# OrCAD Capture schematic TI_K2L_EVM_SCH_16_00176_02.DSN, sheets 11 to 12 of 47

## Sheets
11 PAGE35 : K2L_CLK_GEN1: size C; title: CDCM62008 Clk1, 122.88/19.2, Power Filter for Clock,
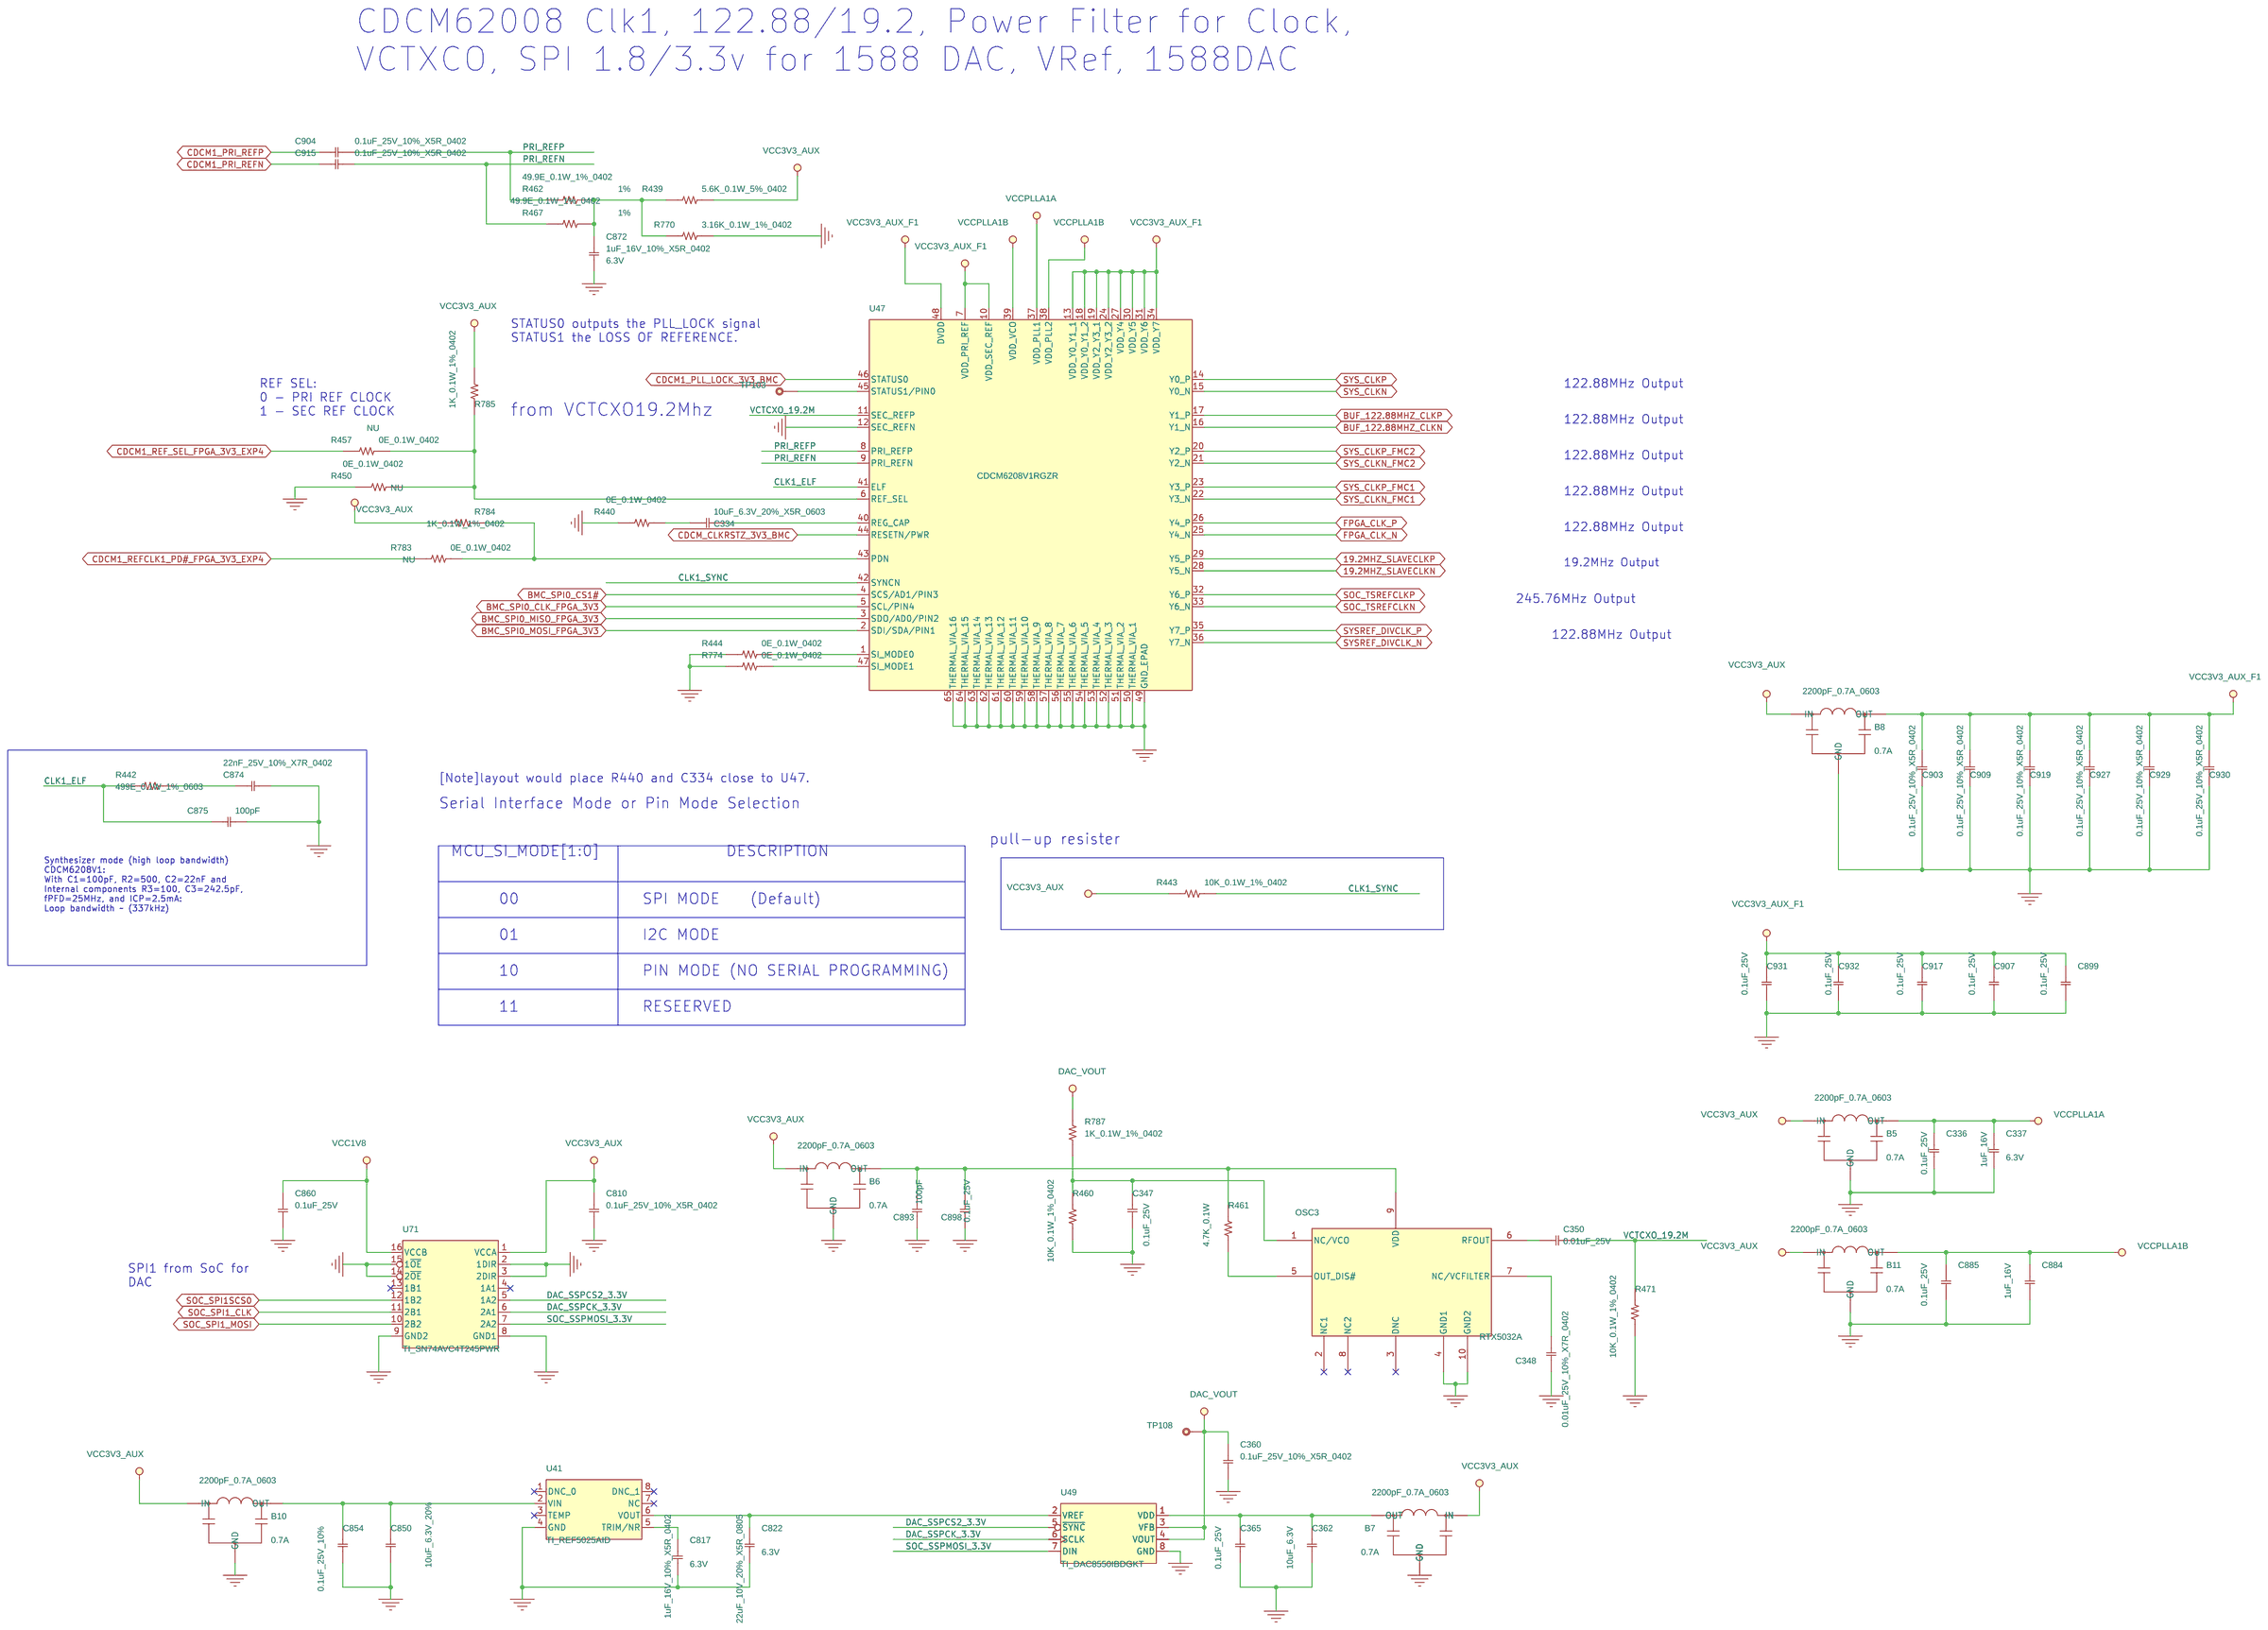
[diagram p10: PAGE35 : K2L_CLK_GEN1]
12 PAGE34 : K2L_ETH_PHY2: size C; title: Ethernet PHY, Magnetics for 2 channel/ Tx/Rx
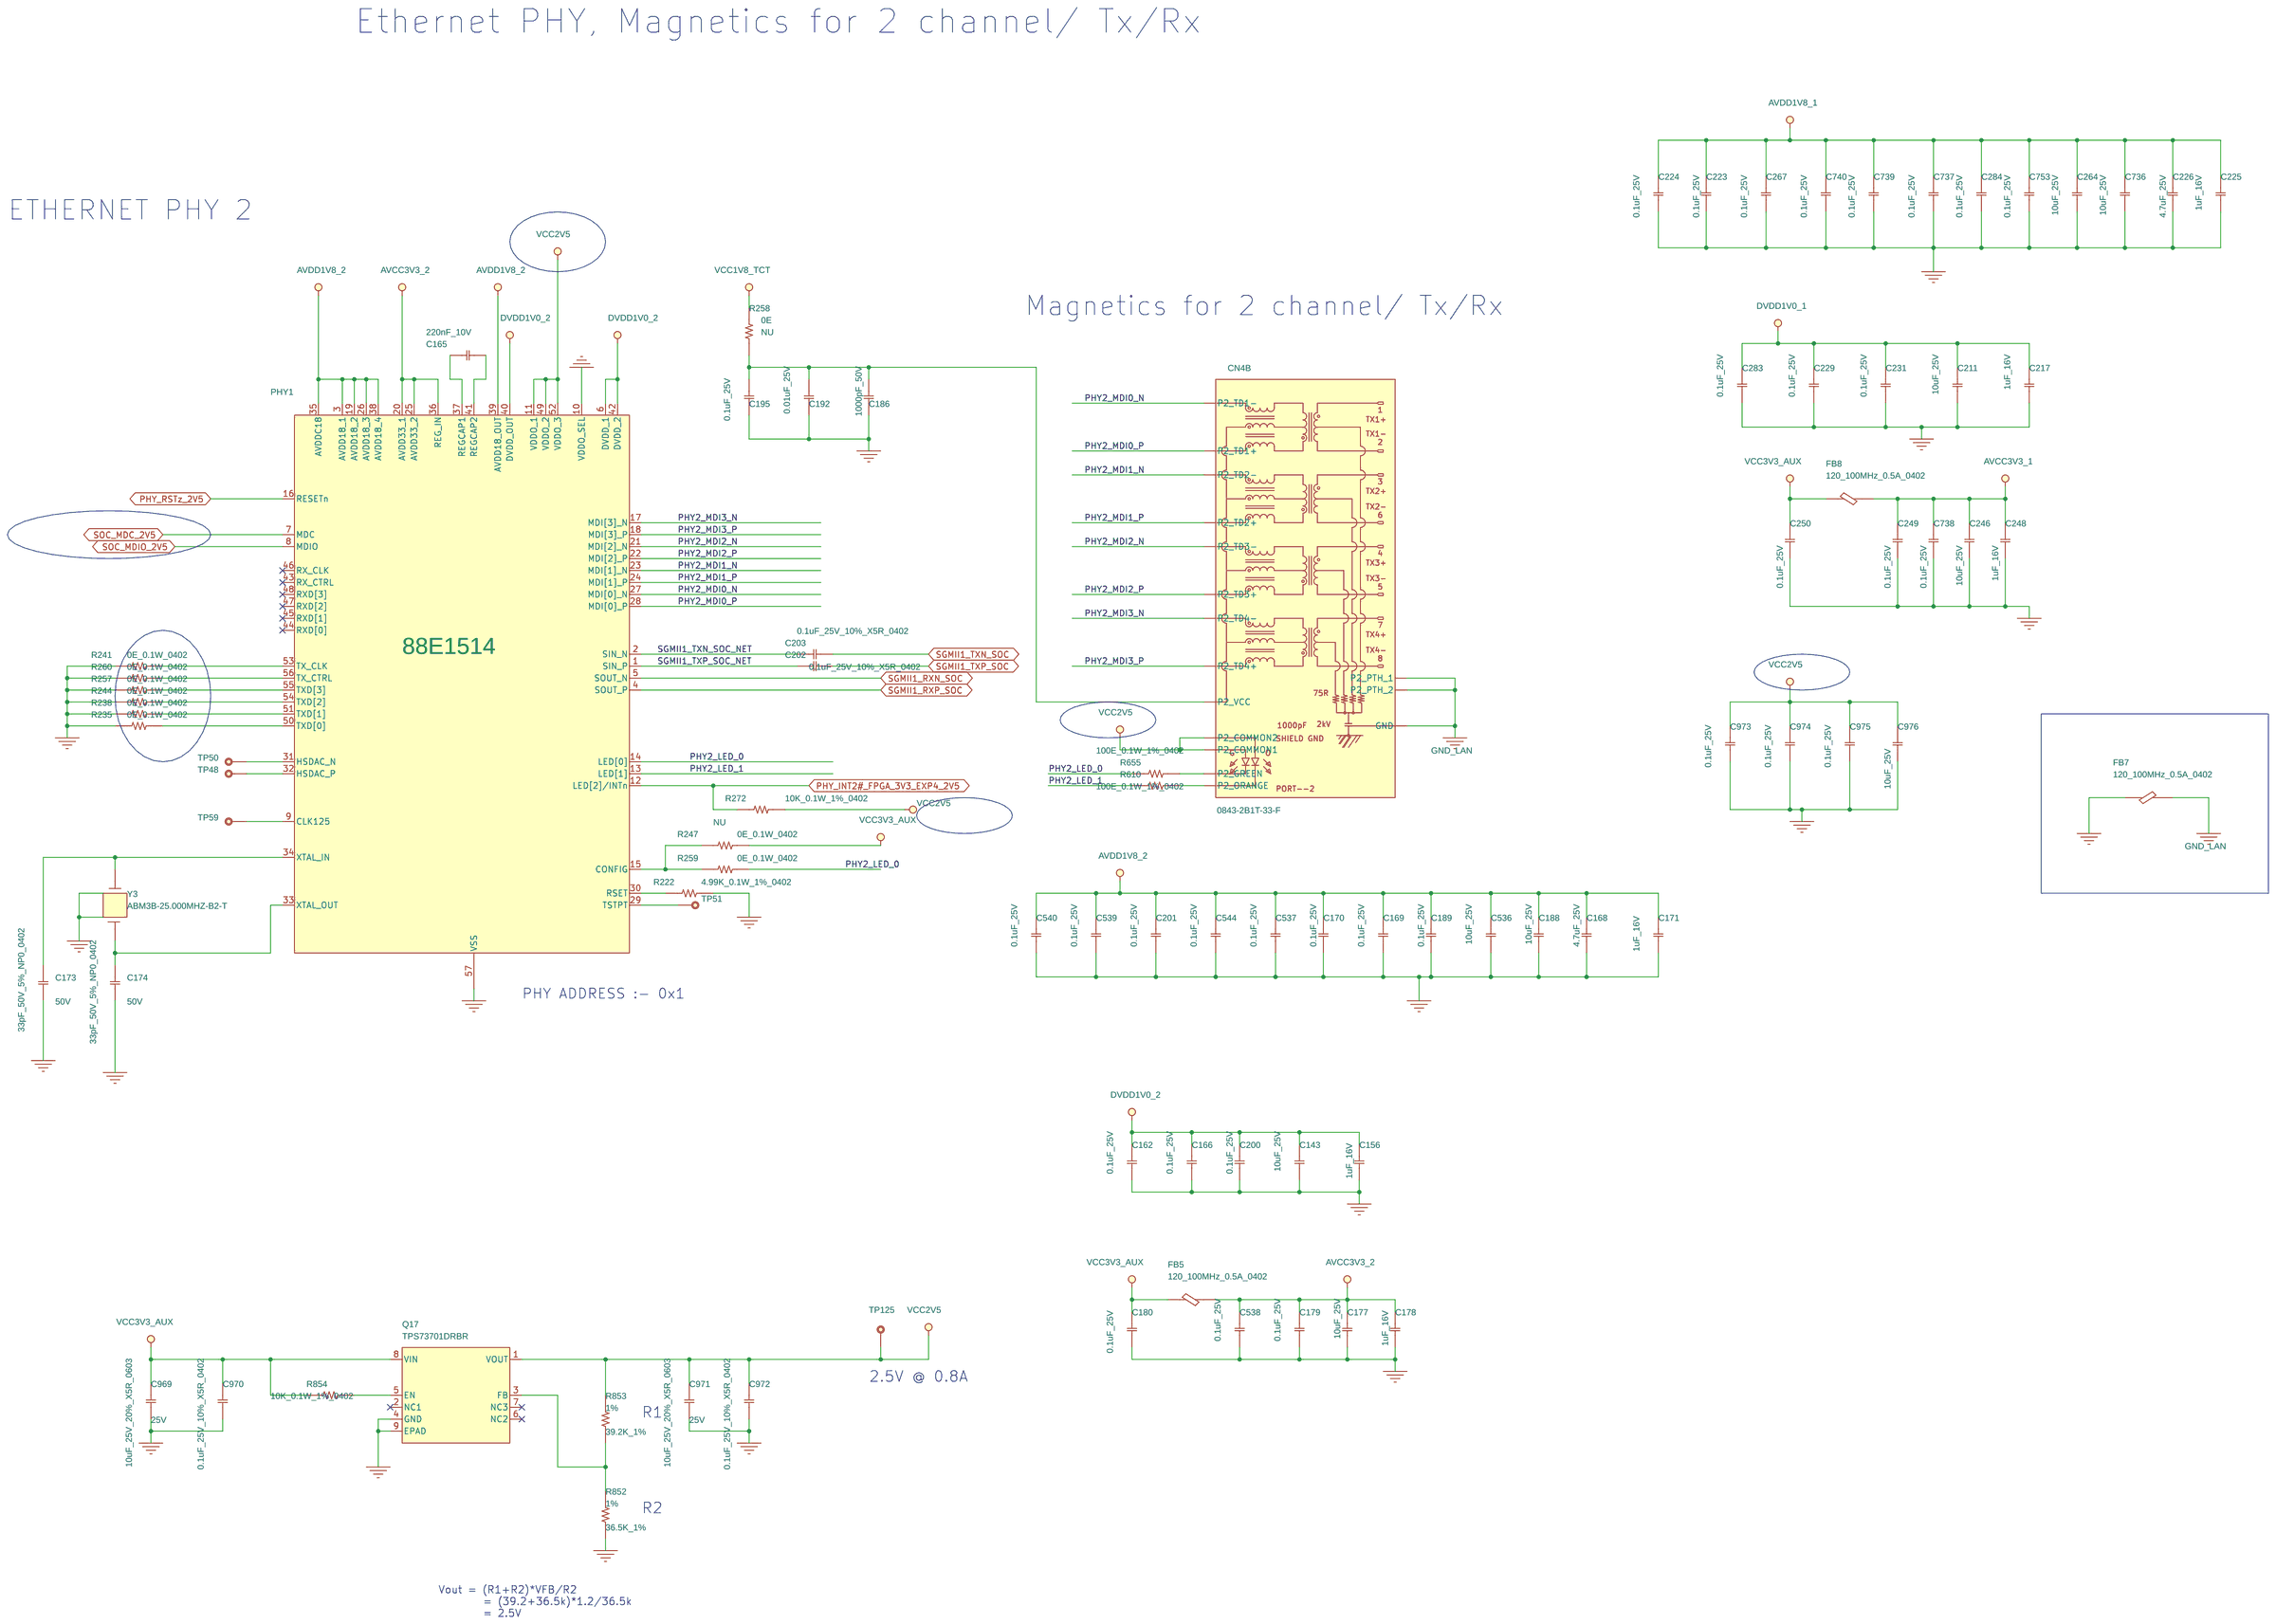
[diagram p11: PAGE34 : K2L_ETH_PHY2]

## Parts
sheet PAGE33 : K2L_ETH_PHY1
CN4  XMH-TRJG17020AENL  [XMULTIPLE_XMH-TRJG17020AENL]  (sections A,B)
sheet PAGE34 : K2L_ETH_PHY2
C143  10uF_25V  [C0603]
C156  1uF_16V  [C0402]
C162  0.1uF_25V  [C0402]
C165  220nF_10V  [C0402]
C166  0.1uF_25V  [C0402]
C168  4.7uF_25V  [C0603]
C169  0.1uF_25V  [C0402]
C170  0.1uF_25V  [C0402]
C171  1uF_16V  [C0402]
C173  33pF_50V_5%_NP0_0402  [C0402]
C174  33pF_50V_5%_NP0_0402  [C0402]
C177  10uF_25V  [C0603]
C178  1uF_16V  [C0402]
C179  0.1uF_25V  [C0402]
C180  0.1uF_25V  [C0402]
C186  1000pF_50V  [C0402]
C188  10uF_25V  [C0603]
C189  0.1uF_25V  [C0402]
C192  0.01uF_25V  [C0402]
C195  0.1uF_25V  [C0402]
C200  0.1uF_25V  [C0402]
C201  0.1uF_25V  [C0402]
C202  0.1uF_25V_10%_X5R_0402  [C0402]
C203  0.1uF_25V_10%_X5R_0402  [C0402]
C211  10uF_25V  [C0603]
C217  1uF_16V  [C0402]
C223  0.1uF_25V  [C0402]
C224  0.1uF_25V  [C0402]
C225  1uF_16V  [C0402]
C226  4.7uF_25V  [C0603]
C229  0.1uF_25V  [C0402]
C231  0.1uF_25V  [C0402]
C246  10uF_25V  [C0603]
C248  1uF_16V  [C0402]
C249  0.1uF_25V  [C0402]
C250  0.1uF_25V  [C0402]
C264  10uF_25V  [C0603]
C267  0.1uF_25V  [C0402]
C283  0.1uF_25V  [C0402]
C284  0.1uF_25V  [C0402]
C536  10uF_25V  [C0603]
C537  0.1uF_25V  [C0402]
C538  0.1uF_25V  [C0402]
C539  0.1uF_25V  [C0402]
C540  0.1uF_25V  [C0402]
C544  0.1uF_25V  [C0402]
C736  10uF_25V  [C0603]
C737  0.1uF_25V  [C0402]
C738  0.1uF_25V  [C0402]
C739  0.1uF_25V  [C0402]
C740  0.1uF_25V  [C0402]
C753  0.1uF_25V  [C0402]
C969  10uF_25V_20%_X5R_0603  [C0603]
C970  0.1uF_25V_10%_X5R_0402  [C0402]
C971  10uF_25V_20%_X5R_0603  [C0603]
C972  0.1uF_25V_10%_X5R_0402  [C0402]
C973  0.1uF_25V  [C0402]
C974  0.1uF_25V  [C0402]
C975  0.1uF_25V  [C0402]
C976  10uF_25V  [C0603]
FB5  120_100MHz_0.5A_0402  [L0402]
FB7  120_100MHz_0.5A_0402  [L0402]
FB8  120_100MHz_0.5A_0402  [L0402]
PHY1  88E1514  [QFN50P800X800X100-57N]
Q17  TPS73701DRBR  [QFN_8P_26_118x118]
R222  4.99K_0.1W_1%_0402  [R0402]
R235  0E_0.1W_0402  [R0402]
R238  0E_0.1W_0402  [R0402]
R241  0E_0.1W_0402  [R0402]
R244  0E_0.1W_0402  [R0402]
R247  0E_0.1W_0402  [R0402]
R257  0E_0.1W_0402  [R0402]
R258  0E  [R0402]
R259  0E_0.1W_0402  [R0402]
R260  0E_0.1W_0402  [R0402]
R272  10K_0.1W_1%_0402  [R0402]
R610  100E_0.1W_1%_0402  [R0402]
R655  100E_0.1W_1%_0402  [R0402]
R852  36.5K_1%  [R0402]
R853  39.2K_1%  [R0402]
R854  10K_0.1W_1%_0402  [R0402]
TP48  TP  [TP-S40]
TP50  TP  [TP-S40]
TP51  TP  [TP-S40]
TP59  TP  [TP-S40]
TP125  Test Point  [TP-S40]
Y3  ABM3B-25.000MHZ-B2-T  [XTAL_ABM3B]
sheet PAGE35 : K2L_CLK_GEN1
B5  2200pF_0.7A_0603  [L_3P_70_63X35]
B6  2200pF_0.7A_0603  [L_3P_70_63X35]
B7  2200pF_0.7A_0603  [L_3P_70_63X35]
B8  2200pF_0.7A_0603  [L_3P_70_63X35]
B10  2200pF_0.7A_0603  [L_3P_70_63X35]
B11  2200pF_0.7A_0603  [L_3P_70_63X35]
C334  10uF_6.3V_20%_X5R_0603  [C0603]
C336  0.1uF_25V  [C0402]
C337  1uF_16V  [C0402]
C347  0.1uF_25V  [C0402]
C348  0.01uF_25V_10%_X7R_0402  [C0402]
C350  0.01uF_25V  [C0402]
C360  0.1uF_25V_10%_X5R_0402  [C0402]
C362  10uF_6.3V  [C0603]
C365  0.1uF_25V  [C0402]
C810  0.1uF_25V_10%_X5R_0402  [C0402]
C817  1uF_16V_10%_X5R_0402  [C0402]
C822  22uF_10V_20%_X5R_0805  [C0805]
C850  10uF_6.3V_20%  [C0603]
C854  0.1uF_25V_10%  [C0402]
C860  0.1uF_25V  [C0402]
C872  1uF_16V_10%_X5R_0402  [C0402]
C874  22nF_25V_10%_X7R_0402  [C0402]
C875  100pF  [C0402]
C884  1uF_16V  [C0402]
C885  0.1uF_25V  [C0402]
C893  100pF  [C0402]
C898  0.1uF_25V  [C0402]
C899  0.1uF_25V  [C0402]
C903  0.1uF_25V_10%_X5R_0402  [C0402]
C904  0.1uF_25V_10%_X5R_0402  [C0402]
C907  0.1uF_25V  [C0402]
C909  0.1uF_25V_10%_X5R_0402  [C0402]
C915  0.1uF_25V_10%_X5R_0402  [C0402]
C917  0.1uF_25V  [C0402]
C919  0.1uF_25V_10%_X5R_0402  [C0402]
C927  0.1uF_25V_10%_X5R_0402  [C0402]
C929  0.1uF_25V_10%_X5R_0402  [C0402]
C930  0.1uF_25V_10%_X5R_0402  [C0402]
C931  0.1uF_25V  [C0402]
C932  0.1uF_25V  [C0402]
OSC3  RTX5032A  [OSCCC320X500X165-10N]
R439  5.6K_0.1W_5%_0402  [R0402]
R440  0E_0.1W_0402  [R0402]
R442  499E_0.1W_1%_0603  [R0603]
R443  10K_0.1W_1%_0402  [R0402]
R444  0E_0.1W_0402  [R0402]
R450  0E_0.1W_0402  [R0402]
R457  0E_0.1W_0402  [R0402]
R460  10K_0.1W_1%_0402  [R0402]
R461  4.7K_0.1W  [R0402]
R462  49.9E_0.1W_1%_0402  [R0402]
R467  49.9E_0.1W_1%_0402  [R0402]
R471  10K_0.1W_1%_0402  [R0402]
R770  3.16K_0.1W_1%_0402  [R0402]
R774  0E_0.1W_0402  [R0402]
R783  0E_0.1W_0402  [R0402]
R784  1K_0.1W_1%_0402  [R0402]
R785  1K_0.1W_1%_0402  [R0402]
R787  1K_0.1W_1%_0402  [R0402]
TP103  TP  [TP-S40]
TP108  TP  [TP-S40]
U41  TI_REF5025AID  [TSSOP65P490_8]
U47  CDCM6208V1RGZR  [QFN_48P_20_276X276_TP161V16]
U49  TI_DAC8550IBDGKT  [SOIC_8P_26_118x193]
U71  TI_SN74AVC4T245PWR  [SOIC_16P_26_197x252]

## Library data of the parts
CN4 = XMH-TRJG17020AENL_0: RJ45 connector with 1000 Base-T Integrated Magnetics; Alt Mfg: Bel Fuse Inc; Alt Mfg Part#: 0879-2C1R-54; Distributor_name: TBD; Distributor_part_number: TBD; EIC Part#: 09_00947_01; Manufacture: X Multiple; Manufacture(English): X Multiple; Manufacturer: X Multiple; Mfg Part#: 09_00947_01; Mfr_name: X Multiple; Vendor: TBD; Vendor_Part_No: TBD; eI Part#: 09_00947_01; CLASS: IO; Color: Default; Location X-Coordinate: 0; Location Y-Coordinate: 0; Primitive: DEFAULT
C143 C177 C188 C211 C246 C264 C536 C736 C969 C971 C976 = 11_C_12: CAP CER 10UF 25V 20% X5R 0603; Characteristic: <Characteristic>; Distributor_name: DIGIKEY; Distributor_part_number: 445-9015-1-ND; EIC Part#: 03_00609_01; Manufacture: TDK Corporation; Manufacture Part Number: C1608X5R1E106M080AC; Manufacture(English): TDK Corporation; Manufacture_Part_Number: C1608X5R1E106M080AC; Manufacturer: TDK Corporation; Manufacturer_Part_No: C1608X5R1E106M080AC; Mfg: TDK Corporation; Mfg Part#: C1608X5R1E106M080AC; Mfr_name: TDK Corporation; Mfr_part_number: C1608X5R1E106M080AC; Oper. Temp. Range: -55C to 85C; Package: 0603; Price @ 1: 0.60000; Price @ 10K: 0.19125; Price @ 1K: 0.19125; ProcessType: SMT; RoHS: Yes; Tolerance: 20%; Vendor: DIGIKEY; Vendor Part#: TDK Corporation; Vendor_Part_No: 445-9015-1-ND; Voltage: 25V; eI Part#: 03_00609_01
C156 C171 C178 C217 C225 C248 = 11_C_12: CAP CER 1UF 16V 10% X5R 0402; Characteristic: <Characteristic>; Distributor_name: DIGIKEY; Distributor_part_number: 445-4978-1-ND; EIC Part#: 03_00355_04; Manufacture: TDK Corporation; Manufacture Part Number: C1005X5R1C105K050BC; Manufacture(English): TDK Corporation; Manufacture_Part_Number: C1005X5R1C105K050BC; Manufacturer: TDK Corporation; Manufacturer_Part_No: C1005X5R1C105K050BC; Mfg: TDK Corporation; Mfg Part#: C1005X5R1C105K050BC; Mfr_name: TDK Corporation; Mfr_part_number: C1005X5R1C105K050BC; Oper. Temp. Range: -55C to 85C; Package: 0402; Price @ 1: 0.12000; Price @ 10K: 0.01600; Price @ 1K: 0.02200; ProcessType: SMT; RoHS: Yes; Tolerance: 10%; Vendor: DIGIKEY; Vendor Part#: 445-4978-1-ND; Vendor_Part_No: 445-4978-1-ND; Voltage: 6.3V; eI Part#: 03_00355_04
C162 C166 C169 C170 C179 C180 C189 C200 C201 C223 C224 C229 C231 C249 C250 C267 C283 C284 C537-C540 C544 C737-C740 C753 C970 C972-C975 = 11_C_12: CAP CER 0.1UF 25V 10% X5R 0402; Alt Mfg: Taiyo Yuden; Distributor_name: DIGIKEY; Distributor_part_number: 445-4964-1-ND; EIC Part#: 03_00470_02; Manufacture: TDK Corporation; Manufacture Part Number: C1005X5R1E104K050BC; Manufacture(English): TDK Corporation; Manufacture_Part_Number: GRM155R61E104KA87D; Manufacturer: TDK Corporation; Manufacturer_Part_No: C1005X5R1E104K050BC; Mfg: Murata Electronics North America; Mfg Part#: 03_00470_02; Mfr_name: TDK Corporation; Mfr_part_number: C1005X5R1E104K050BC; Oper. Temp. Range: -55°C ~ 85°C; Package: 0402; Price @ 1: 0.10000; Price @ 1K: 0.00960; ProcessType: SMT; RoHS: Yes; Tolerance: 10%; Vendor: DIGIKEY; Vendor Part#: 445-4964-1-ND; Vendor_Part_No: 445-4964-1-ND; eI Part#: 03_00470_02
C165 = Cap_Ceramic: CAP CER 0.22UF 10V 10% X5R 0402; Alt Mfg: Taiyo Yuden; Alt Mfg Part#: TMK105BJ104KV-F; Distributor_name: DIGIKEY; Distributor_part_number: 445-4985-1-ND; EIC Part#: TBD; MOUNTED: <MOUNTED>; Manufacture: TDK Corporation; Manufacture Part Number: C1005X5R1A224K050BC; Manufacture(English): TDK Corporation; Manufacturer: TDK Corporation; Manufacturer_Part_No: C1005X5R1A224K050BC; Mfg: TDK Corporation; Mfg Part#: TBD; Mfr_name: TDK Corporation; Mfr_part_number: C1005X5R1A224K050BC; Oper. Temp. Range: -55°C ~ 85°C; Package: 0402; ProcessType: SMT; RoHS: Yes; Tolerance: 10%; Vendor: DIGIKEY; Vendor Part#: 445-4985-1-ND; Vendor_Part_No: 445-4985-1-ND; Voltage: 10V; eI Part#: TBD
C168 C226 = 11_C_12: CAP CER 4.7UF 25V 20% X5R 0603; Characteristic: <Characteristic>; Distributor_name: DIGIKEY; Distributor_part_number: 1276-1903-2-ND; EIC Part#: 03_00592_01; Manufacture: Samsung; Manufacture Part Number: CL10A475MA8NQNC; Manufacture(English): Samsung; Manufacture_Part_Number: CL10A475MA8NQNC; Manufacturer: Samsung; Manufacturer_Part_No: CL10A475MA8NQNC; Mfg: Samsung; Mfg Part#: CL10A475MA8NQNC; Mfr_name: Samsung; Mfr_part_number: CL10A475MA8NQNC; Oper. Temp. Range: -55C to 85C; Package: 0603; Price @ 1: 0.16000; Price @ 10K: 0.02322; Price @ 1K: 0.02970; ProcessType: SMT; RoHS: Yes; Tolerance: 10%; Vendor: DIGIKEY; Vendor Part#: 1276-1903-2-ND; Vendor_Part_No: 1276-1903-2-ND; Voltage: 6.3V; eI Part#: 03_00592_01
C173 C174 = 11_C_12: CAP CER 33PF 50V 5% NPO 0402; Characteristic: <Characteristic>; Distributor_name: DIGIKEY; Distributor_part_number: 311-1020-1-ND; EIC Part#: 03_00019_01; Manufacture: Yageo; Manufacture Part Number: CC0402JRNPO9BN330; Manufacture(English): Yageo; Manufacture_Part_Number: CC0402JRNPO9BN330; Manufacturer: Yageo; Manufacturer_Part_No: CC0402JRNPO9BN330; Mfg: Yageo; Mfg Part#: 03_00019_01; Mfr_name: Yageo; Mfr_part_number: CC0402JRNPO9BN330; Oper. Temp. Range: -55C to 85C; Package: 0402; Price @ 1: 0.10000; Price @ 10K: 0.00227; Price @ 1K: 0.00324; ProcessType: SMT; RoHS: Yes; Tolerance: 10%; Vendor: DIGIKEY; Vendor Part#: 311-1020-1-ND; Vendor_Part_No: 311-1020-1-ND; Voltage: 50V; eI Part#: 03_00019_01
C186 = 11_C_0: CAP CER 1000PF 50V 10% X7R 0402; Advansus_Part_Number: 11G232110214030; Distributor_name: DIGIKEY; Distributor_part_number: 1276-1493-1-ND; EIC Part#: 03_00591_01; Manufacture: Samsung; Manufacture Part Number: CL05B102KB5NFNC; Manufacture(English): Samsung; Manufacture_Part_Number: CL05B102KB5NFNC; Manufacturer: Samsung; Manufacturer_Part_No: CL05B102KB5NFNC; Mfg: Samsung; Mfg Part#: CL05B102KB5NFNC; Mfr_name: Samsung; Mfr_part_number: CL05B102KB5NFNC; Oper. Temp. Range: -55C to 85C; Package: 0402; Price @ 1: 0.10000; Price @ 10K: 0.00260; Price @ 1K: 0.00372; ProcessType: SMT; RoHS: Yes; Tolerance: 10%; Vendor: DIGIKEY; Vendor Part#: 1276-1493-1-ND; Vendor_Part_No: 1276-1493-1-ND; Voltage: 50V; eI Part#: 03_00591_01
C192 C348 C350 = 11_C_0: CAP CER 10000PF 25V 10% X7R 0402; Alt Mfg: Murata; Alt Mfg Part#: GRM155R71C103KA01D; Distributor_name: DIGIKEY; Distributor_part_number: 445-1260-1-ND; EIC Part#: 03_00029_04; Manufacture: TDK Corporation; Manufacture Part Number: C1005X7R1E103K; Manufacture(English): TDK Corporation; Manufacture_Part_Number: C1005X7R1E103K; Manufacturer: TDK Corporation; Manufacturer_Part_No: C1005X7R1E103K; Mfg: TDK Corporation; Mfg Part#: 03_00029_04; Mfr_name: TDK Corporation; Mfr_part_number: C1005X7R1E103K; Oper. Temp. Range: -55C to 125C; Package: 0402; Price @ 1: 0.10000; Price @ 10K: 0.00420; Price @ 1K: 0.00600; ProcessType: SMT; RoHS: Yes; Tolerance: 10%; Vendor: DIGIKEY; Vendor Part#: PCC103BQCT-ND; Vendor_Part_No: 445-1260-1-ND; Voltage: 16V; eI Part#: 03_00029_04
C195 = 11_C_12: CAP CER 0.1UF 25V 10% X5R 0402; Alt Mfg: Taiyo Yuden; Distributor_name: DIGIKEY; Distributor_part_number: 445-4964-1-ND; EIC Part#: 03_00470_02; MOUNTED: <MOUNTED>; Manufacture: TDK Corporation; Manufacture Part Number: C1005X5R1E104K050BC; Manufacture(English): TDK Corporation; Manufacture_Part_Number: GRM155R61E104KA87D; Manufacturer: TDK Corporation; Manufacturer_Part_No: C1005X5R1E104K050BC; Mfg: Murata Electronics North America; Mfg Part#: 03_00470_02; Mfr_name: TDK Corporation; Mfr_part_number: C1005X5R1E104K050BC; Oper. Temp. Range: -55°C ~ 85°C; Package: 0402; Price @ 1: 0.10000; Price @ 1K: 0.00960; ProcessType: SMT; RoHS: Yes; Vendor: DIGIKEY; Vendor Part#: 445-4964-1-ND; Vendor_Part_No: 445-4964-1-ND; eI Part#: 03_00470_02
C202 C203 = 11_C_12: CAP CER 0.1UF 25V 10% X5R 0402; Alt Mfg: Taiyo Yuden; Distributor_name: DIGIKEY; Distributor_part_number: 445-4964-1-ND; EIC Part#: 03_00470_02; MOUNTED: <MOUNTED>; Manufacture: TDK Corporation; Manufacture Part Number: C1005X5R1E104K050BC; Manufacture(English): TDK Corporation; Manufacture_Part_Number: GRM155R61E104KA87D; Manufacturer: TDK Corporation; Manufacturer_Part_No: C1005X5R1E104K050BC; Mfg: Murata Electronics North America; Mfg Part#: 03_00470_02; Mfr_name: TDK Corporation; Mfr_part_number: C1005X5R1E104K050BC; Oper. Temp. Range: -55°C ~ 85°C; Package: 0402; Price @ 1: 0.10000; Price @ 1K: 0.00960; ProcessType: SMT; RoHS: Yes; Tolerance: 10%; Vendor: DIGIKEY; Vendor Part#: 445-4964-1-ND; Vendor_Part_No: 445-4964-1-ND; eI Part#: 03_00470_02
FB5 FB7 FB8 = 1212_BEAD_0: FERRITE CHIP 120 OHM 500MA 0402; Distributor_name: DIGIKEY; Distributor_part_number: 490-1005-1-ND; EIC Part#: 04_00075_01; Manufacture: Murata; Manufacture Part Number: BLM15AG121SN1D; Manufacture(English): Murata; Manufacture_Part_Number: BLM15AG121SN1D; Manufacturer: Murata; Manufacturer_Part_No: BLM15AG121SN1D; Mfg: Murata Electronics North America; Mfg Part#: BLM15AG121SN1D; Mfr_name: Murata; Mfr_part_number: BLM15AG121SN1D; Oper. Temp. Range: -55C to 85C; Package: 0402; Price @ 1: 0.10000; Price @ 10K: 0.02016; Price @ 1K: 0.02905; ProcessType: SMT; RoHS: Yes; Tolerance: 25%; Vendor: DIGIKEY; Vendor Part#: 490-1005-1-ND; Vendor_Part_No: 490-1005-1-ND; eI Part#: 04_00075_01
PHY1 = 88E1512: Alt Mfg: MARVELL; Alt Mfg Part#: 88E1512-A0-NNP2C000; Distributor_name: Avnet Express; Distributor_part_number: 88E1514-XX-NNP2C000; EIC Part#: TBD; Manufacture: Marvell; Manufacture Part Number: 88E1514-XX-NNP2C000; Manufacture(English): Marvell; Manufacture_Part_Number: 88E1514-XX-NNP2C000; Manufacturer: Marvell; Manufacturer_Part_No: 88E1514-XX-NNP2C000; Mfg: Marvell; Mfg Part#: TBD; Mfr_name: Marvell; Mfr_part_number: 88E1514-XX-NNP2C000; Price @ 1: TBD; Price @ 10K: TBD; Price @ 1K: TBD; Vendor: Avnet Express; Vendor Part#: 88E1514-XX-NNP2C000; Vendor_Part_No: 88E1514-XX-NNP2C000; eI Part#: TBD
Q17 = TPS73701DRBT: IC REG LDO ADJ 1A 8SON; Distributor_name: DIGIKEY; Distributor_part_number: 296-22065-1-ND; EIC Part#: 01_00822_01; Manufacture: TI; Manufacture(English): TI; Manufacturer: TI; Mfg: TI; Mfg Part#: 01_00822_01; Mfr_name: TI; Oper. Temp. Range: -40°C ~ 125°C; Package: SON8; Price @ 1: 1.72000; Price @ 10K: 0.67500; Price @ 1K: 0.68851; ProcessType: SMT; RoHS: Yes; Vendor: DIGIKEY; Vendor Part#: 296-27067-1-ND; Vendor_Part_No: 296-22065-1-ND; eI Part#: 01_00822_01
R222 = 10_R_0: RES 4.99K OHM 1/10W 1% 0402 SMD; Alt Mfg: Yageo; Alt Mfg Part#: RC0402FR-071KL; Distributor_name: DIGIKEY; Distributor_part_number: P4.99KLCT-ND; EIC Part#: 02_00038_01; MOUNTED: <MOUNTED>; Manufacture: Panasonic - ECG; Manufacture Part Number: ERJ-2RKF4991X; Manufacture(English): Panasonic - ECG; Manufacture_Part_Number: ERJ-2RKF4991X; Manufacturer: Panasonic - ECG; Manufacturer_Part_No: ERJ-2RKF4991X; Mfg Part#: 02_00038_01; Mfr_name: Panasonic - ECG; Mfr_part_number: ERJ-2RKF4991X; Oper. Temp. Range: -55C to 125C; Package: 0402; ProcessType: SMT; RoHS: Yes; Tolerance: 1%; Vendor: DIGIKEY; Vendor Part#: P4.99KLCT-ND; Vendor_Part_No: P4.99KLCT-ND; eI Part#: TBD
R235 R238 R241 R244 R257 R259 R260 = 10_R_0: RES 0.0 OHM 1/10W JUMP 0402 SMD; Alt Mfg: Yageo; Distributor_name: DIGIKEY; Distributor_part_number: P0.0JCT-ND; EIC Part#: 02_00019_01; Manufacture: Panasonic - ECG; Manufacture Part Number: ERJ-2GE0R00X; Manufacture(English): Panasonic - ECG; Manufacture_Part_Number: ERJ-2GE0R00X; Manufacturer: Panasonic - ECG; Manufacturer_Part_No: ERJ-2GE0R00X; Mfg Part#: 02_00019_01; Mfr_name: Panasonic - ECG; Mfr_part_number: ERJ-2GE0R00X; Oper. Temp. Range: -55C to 125C; Package: 0402; ProcessType: SMT; Remark: Alt part is 1/16W; RoHS: Yes; Tolerance: 5%; Vendor: DIGIKEY; Vendor Part#: P0.0JCT-ND; Vendor_Part_No: P0.0JCT-ND; eI Part#: 02_00019_01
R247 = 10_R_0: RES 0.0 OHM 1/10W JUMP 0402 SMD; Alt Mfg: Yageo; Distributor_name: DIGIKEY; Distributor_part_number: P0.0JCT-ND; EIC Part#: 02_00019_01; Manufacture: Panasonic - ECG; Manufacture Part Number: ERJ-2GE0R00X; Manufacture(English): Panasonic - ECG; Manufacture_Part_Number: ERJ-2GE0R00X; Manufacturer: Panasonic - ECG; Manufacturer_Part_No: ERJ-2GE0R00X; Mfg Part#: 02_00019_01; Mfr_name: Panasonic - ECG; Mfr_part_number: ERJ-2GE0R00X; Mounting: NU; Mounting Status: NU; Mounting_Status: NU; Oper. Temp. Range: -55C to 125C; Package: 0402; ProcessType: SMT; Remark: Alt part is 1/16W; RoHS: Yes; Tolerance: 5%; Vendor: DIGIKEY; Vendor Part#: P0.0JCT-ND; Vendor_Part_No: P0.0JCT-ND; eI Part#: 02_00019_01
R258 = 10_R_0: RES 0.0 OHM 1/10W JUMP 0402 SMD; Characteristic: 5%; Distributor_name: DIGIKEY; Distributor_part_number: P0.0JCT-ND; EIC Part#: 02_00019_01; Manufacture: Panasonic - ECG; Manufacture Part Number: ERJ-2GE0R00X; Manufacture(English): Panasonic - ECG; Manufacture_Part_Number: ERJ-2GE0R00X; Manufacturer: Panasonic - ECG; Manufacturer_Part_No: ERJ-2GE0R00X; Mfg: Panasonic Electronic Components; Mfg Part#: 02_00019_01; Mfr_name: Panasonic - ECG; Mfr_part_number: ERJ-2GE0R00X; Mounting: NU; Mounting Status: NU; Mounting_Status: NU; Package: 0402; Part_Number: 105A700004; Price @ 1: 0.05000; Price @ 10K: 0.00248; Price @ 1K: 0.00480; ProcessType: SMT; Tolerance: 5%; Vendor: DIGIKEY; Vendor_Part_No: P0.0JCT-ND; eI Part#: 02_00019_01
R272 R854 = 10_R_0: RES 10K OHM 1/10W 1% 0402 SMD; Alt Mfg: Yageo; Alt Mfg Part#: RC0402FR-0710KL; Distributor_name: DIGIKEY; Distributor_part_number: P10.0KLCT-ND; EIC Part#: 02_00027_01; Manufacture: Panasonic - ECG; Manufacture Part Number: ERJ-2RKF1002X; Manufacture(English): Panasonic - ECG; Manufacture_Part_Number: ERJ-2RKF1002X; Manufacturer: Panasonic - ECG; Manufacturer_Part_No: ERJ-2RKF1002X; Mfg Part#: 02_00027_01; Mfr_name: Panasonic - ECG; Mfr_part_number: ERJ-2RKF1002X; Oper. Temp. Range: -55C ~ 125C; Package: 0402; Price @ 1: 0.10000; Price @ 10K: 0.00347; Price @ 1K: 0.00672; ProcessType: SMT; Remark: Alt part is 1/16W; RoHS: Yes; Tolerance: 1%; Vendor: DIGIKEY; Vendor Part#: P10.0KLCT-ND; Vendor_Part_No: P10.0KLCT-ND; eI Part#: 02_00027_01
R610 R655 = 10_R_0: RES 100 OHM 1/10W 1% 0402 SMD; Distributor_name: DIGIKEY; Distributor_part_number: P100LCT-ND; EIC Part#: 02_00043_02; Manufacture: Panasonic - ECG; Manufacture Part Number: ERJ-2RKF1000X; Manufacture(English): Panasonic - ECG; Manufacture_Part_Number: ERJ-2RKF1000X; Manufacturer: Panasonic - ECG; Manufacturer_Part_No: ERJ-2RKF1000X; Mfg Part#: 02_00043_02; Mfr_name: Panasonic - ECG; Mfr_part_number: ERJ-2RKF1000X; Oper. Temp. Range: -55C to 125C; Package: 0402; ProcessType: SMT; RoHS: Yes; Tolerance: 1%; Vendor: DIGIKEY; Vendor Part#: P100LCT-ND; Vendor_Part_No: P100LCT-ND; eI Part#: 02_00019_01
R852 = 10_R_0: RES 36.5K OHM 1/10W 1% 0402 SMD; Distributor_name: DIGIKEY; Distributor_part_number: P36.5KLCT-ND; EIC Part#: TBD; Manufacture: Panasonic - ECG; Manufacture Part Number: ERJ-2RKF3652X; Manufacture(English): Panasonic - ECG; Manufacture_Part_Number: ERJ-2RKF3652X; Manufacturer: Panasonic - ECG; Manufacturer_Part_No: ERJ-2RKF3652X; Mfg: Panasonic - ECG; Mfg Part#: ERJ-2RKF3652X; Mfr_name: Panasonic - ECG; Mfr_part_number: ERJ-2RKF3652X; Oper. Temp. Range: -55C ~ 125C; Package: 0402; ProcessType: SMT; RoHS: Yes; Tolerance: 1%; Vendor: DigiKey; Vendor Part#: P36.5KLCT-ND; Vendor_Part_No: P36.5KLCT-ND; eI Part#: TBD
R853 = 10_R_0: RES 39.2K OHM 1/10W 1% 0402 SMD; Distributor_name: DIGIKEY; Distributor_part_number: P39.2KLCT-ND; EIC Part#: TBD; Manufacture: Panasonic - ECG; Manufacture Part Number: ERJ-2RKF3922X; Manufacture(English): Panasonic - ECG; Manufacture_Part_Number: ERJ-2RKF3922X; Manufacturer: Panasonic - ECG; Manufacturer_Part_No: ERJ-2RKF3922X; Mfg: Panasonic - ECG; Mfg Part#: ERJ-2RKF3922X; Mfr_name: Panasonic - ECG; Mfr_part_number: ERJ-2RKF3922X; Oper. Temp. Range: -55C ~ 125C; Package: 0402; ProcessType: SMT; RoHS: Yes; Tolerance: 1%; Vendor: DigiKey; Vendor Part#: P39.2KLCT-ND; Vendor_Part_No: P39.2KLCT-ND; eI Part#: TBD
TP48 TP50 TP51 TP59 = 00_TP-S40_0: TEST PAD TP; Distributor_name: NA; Distributor_part_number: NA; EIC Part#: NA; Manufacture: NA; Manufacture Part Number: NA; Manufacture(English): NA; Manufacture_Part_Number: NA; Manufacturer: NA; Manufacturer_Part_No: NA; Mfg: NA; Mfg Part#: NA; Mfr_name: NA; Mfr_part_number: NA; Oper. Temp. Range: --NA--; Package: --NA--; Price @ 1: NA; Price @ 10K: NA; Price @ 1K: NA; ProcessType: SMT; RoHS: Yes; Vendor: NA; Vendor Part#: --NA--; Vendor_Part_No: NA; eI Part#: NA
TP125 = 00_TP-S40_0: TEST PAD TP-S40; Mfg: --NA--; Mfg Part#: --NA--; Oper. Temp. Range: --NA--; Package: --NA--; ProcessType: SMT; RoHS: Yes; Vendor: --NA--; Vendor Part#: --NA--; eI Part#: --NA--
Y3 = CRYSTAL-4_PIN: CRYSTAL 25MHZ 18PF SMD; Distributor_name: DIGIKEY; Distributor_part_number: 535-9128-1-ND; EIC Part#: 08_00006_01; Manufacture: Abracon Corporation; Manufacture(English): Abracon Corporation; Manufacturer: Abracon Corporation; Mfg: Abracon Corporation; Mfg Part#: 08_00006_01; Mfr_name: Abracon Corporation; Oper. Temp. Range: -20C to 60C; Package: 5.0mm x 3.2mm; Price @ 1: 1.43000; Price @ 10K: 0.53200; Price @ 1K: 0.53200; RoHS: Yes; Specifications: CRYSTAL 25.000MHZ 18PF FUND SMD; Vendor: DIGIKEY; Vendor Part#: 535-9128-1-ND; Vendor_Part_No: 535-9128-1-ND; eI Part#: 08_00006_01
B5-B8 B10 B11 = 1212_FILTER_NFW31SP106X1E4L_0: EMI Filter 0.7A SMD 3P NFM18CC222R1C3; Characteristic: 0.7A; Distributor_name: DIGIKEY; Distributor_part_number: 490-6965-1-ND; EIC Part#: 04_00026_01; Manufacture: Murata; Manufacture Part Number: NFM18CC222R1C3D; Manufacture(English): Murata; Manufacture_Part_Number: NFM18CC222R1C3D; Manufacturer: Murata; Manufacturer_Part_No: NFM18CC222R1C3D; Mfg: Murata Electronics North America; Mfg Part#: 04_00026_01; Mfr_name: Murata; Mfr_part_number: NFM18CC222R1C3D; Package: 0603; Part_Number: 1212002287; Price @ 1: 0.28000; Price @ 10K: 0.09855; Price @ 1K: 0.11242; ProcessType: SMT; Tolerance: 20%; Vendor: DIGIKEY; Vendor_Part_No: 490-6965-1-ND; eI Part#: 04_00026_01
C334 C362 C850 = 11_C_0: CAP CER 10UF 6.3V 20% X5R 0603; Avalue_Part_Number: E1121610610H; Characteristic: 6.3V; Distributor_name: DIGIKEY; Distributor_part_number: 587-3383-1-ND; EIC Part#: 03_00605_01; Manufacture: Taiyo Yuden; Manufacture Part Number: JMK107ABJ106MAHT; Manufacture(English): Taiyo Yuden; Manufacture_Part_Number: JMK107ABJ106MAHT; Manufacturer: Taiyo Yuden; Manufacturer_Part_No: JMK107ABJ106MAHT; Mfg: Taiyo Yuden; Mfg Part#: JMK107ABJ106MAHT; Mfr_name: Taiyo Yuden; Mfr_part_number: JMK107ABJ106MAHT; Package: 0603; Part_Number: 1100004184; Price @ 1: 0.32000; Price @ 10K: 0.06105; Price @ 1K: 0.07755; ProcessType: SMT; Tolerance: 20%; Vendor: DIGIKEY; Vendor Part#: 587-3383-1-ND; Vendor_Part_No: 587-3383-1-ND; eI Part#: 03_00605_01
C336 C347 C360 C365 C810 C854 C860 C885 C898 C899 C903 C904 C907 C909 C915 C917 C919 C927 C929-C932 = 11_C_0: CAP CER 0.1UF 25V 10% X5R 0402; Avalue_Part_Number: E1123510400H; Distributor_name: DIGIKEY; Distributor_part_number: 445-4964-1-ND; EIC Part#: 03_00470_02; MOUNTED: <MOUNTED>; Manufacture: TDK Corporation; Manufacture Part Number: C1005X5R1E104K050BC; Manufacture(English): TDK Corporation; Manufacture_Part_Number: GRM155R71C104KA88D; Manufacturer: TDK Corporation; Manufacturer_Part_No: C1005X5R1E104K050BC; Mfg: Murata Electronics North America; Mfg Part#: 03_00470_02; Mfr_name: TDK Corporation; Mfr_part_number: C1005X5R1E104K050BC; Package: 0402; Price @ 1: 0.10000; Price @ 1K: 0.00420; ProcessType: SMT; Tolerance: 10%; Vendor: DIGIKEY; Vendor Part#: 445-4964-1-ND; Vendor_Part_No: 445-4964-1-ND; eI Part#: 03_00470_02
C337 C817 C872 C884 = 11_C_0: CAP CER 1UF 16V 10% X5R 0402; Characteristic: 6.3V; Distributor_name: DIGIKEY; Distributor_part_number: 445-4978-1-ND; EIC Part#: 03_00355_04; Manufacture: TDK Corporation; Manufacture Part Number: C1005X5R1C105K050BC; Manufacture(English): TDK Corporation; Manufacture_Part_Number: C1005X5R1C105K050BC; Manufacturer: TDK Corporation; Manufacturer_Part_No: C1005X5R1C105K050BC; Mfg: TDK Corporation; Mfg Part#: C1005X5R1C105K050BC; Mfr_name: TDK Corporation; Mfr_part_number: C1005X5R1C105K050BC; Package: 0402; Part_Number: 1100000870; Price @ 1: 0.10000; Price @ 10K: 0.01155; Price @ 1K: 0.01650; ProcessType: SMT; Tolerance: 10%; Vendor: DIGIKEY; Vendor_Part_No: 445-4978-1-ND; eI Part#: 03_00355_04
C822 = 11_C_0: CAP CER 22UF 10V 20% X5R 0805; Characteristic: 6.3V; Distributor_name: DIGIKEY; Distributor_part_number: 587-1958-1-ND; EIC Part#: 03_00263_01; Manufacture: Taiyo Yuden; Manufacture Part Number: LMK212BJ226MG-T; Manufacture(English): Taiyo Yuden; Manufacture_Part_Number: LMK212BJ226MG-T; Manufacturer: Taiyo Yuden; Manufacturer_Part_No: LMK212BJ226MG-T; Mfg: Taiyo Yuden; Mfg Part#: 03_00263_01; Mfr_name: Taiyo Yuden; Mfr_part_number: LMK212BJ226MG-T; Package: 0805; Part_Number: 1100000254; Price @ 1: 0.53000; Price @ 10K: 0.12000; Price @ 1K: 0.16875; ProcessType: SMT; Tolerance: 20%; Vendor: DIGIKEY; Vendor Part#: 587-1958-1-ND; Vendor_Part_No: 587-1958-1-ND; eI Part#: 03_00263_01
C874 = 11_C_0: CAP CER 0.022UF 25V 10% X7R 0402; Characteristic: 25V; Distributor_name: DIGIKEY; Distributor_part_number: 445-1261-1-ND; EIC Part#: 03_00565_02; Manufacture: TDK Corporation; Manufacture Part Number: C1005X7R1E223K050BB; Manufacture(English): TDK Corporation; Manufacture_Part_Number: C1005X7R1E223K050BB; Manufacturer: TDK Corporation; Manufacturer_Part_No: C1005X7R1E223K050BB; Mfg: TDK Corporation; Mfg Part#: TBD; Mfr_name: TDK Corporation; Mfr_part_number: C1005X7R1E223K050BB; Package: 0402; Price @ 1: 0.10000; Price @ 10K: 0.00759; Price @ 1K: 0.00990; ProcessType: SMT; RoHS: Yes; Tolerance: 10%; Vendor: DIGIKEY; Vendor Part#: 445-1261-1-ND; Vendor_Part_No: 445-1261-1-ND; Voltage: 25V; eI Part#: 03_00565_02
C875 = 11_C_12: CAP CER 100PF 50V 5% NP0 0402; Characteristic: <Characteristic>; Distributor_name: DIGIKEY; Distributor_part_number: 490-5922-1-ND; EIC Part#: 03_00594_01; Manufacture: Murata; Manufacture Part Number: GRM1555C1H101JA01D; Manufacture(English): 490-5922-1-ND; Manufacture_Part_Number: GRM1555C1H101JA01D; Manufacturer: Murata; Manufacturer_Part_No: GRM1555C1H101JA01D; Mfg: Murata; Mfg Part#: GRM1555C1H101JA01D; Mfr_name: Murata; Mfr_part_number: GRM1555C1H101JA01D; Oper. Temp. Range: -55°C ~ 125°C; Package: 0402; Price @ 1: 0.10000; Price @ 10K: 0.00500; Price @ 1K: 0.00600; ProcessType: SMT; RoHS: Yes; Tolerance: 5%; Vendor: DIGIKEY; Vendor Part#: 490-5922-1-ND; Vendor_Part_No: 490-5922-1-ND; Voltage: 50V; eI Part#: 03_00594_01
C893 = 11_C_0: CAP CER 100PF 50V 5% NP0 0402; Characteristic: 50V; Distributor_name: DIGIKEY; Distributor_part_number: 490-5922-1-ND; EIC Part#: 03_00594_01; Manufacture: Murata; Manufacture Part Number: GRM1555C1H101JA01D; Manufacture(English): 490-5922-1-ND; Manufacture_Part_Number: GRM1555C1H101JA01D; Manufacturer: Murata; Manufacturer_Part_No: GRM1555C1H101JA01D; Mfg: Murata; Mfg Part#: GRM1555C1H101JA01D; Mfr_name: Murata; Mfr_part_number: GRM1555C1H101JA01D; Package: 0402; Price @ 1: 0.10000; Price @ 10K: 0.00500; Price @ 1K: 0.00600; ProcessType: SMT; Tolerance: 5%; Vendor: DIGIKEY; Vendor Part#: 490-5922-1-ND; Vendor_Part_No: 490-5922-1-ND; eI Part#: 03_00594_01
OSC3 = RTX5032A_0: SMD Temperature Compensated Crystal Oscillator; Distributor_name: NA; Distributor_part_number: NA; EIC Part#: TBD; Manufacture: Rakon; Manufacture Part Number: RTX5032A 19.200 MHz; Manufacture(English): Rakon; Manufacture_Part_Number: RTX5032A 19.200 MHz; Manufacturer: Rakon; Manufacturer_Part_No: RTX5032A 19.200 MHz; Mfg: Rakon; Mfg Part#: RTX5032A 19.200 MHz; Mfr_name: Rakon; Mfr_part_number: RTX5032A 19.200 MHz; Price @ 1: TBD; Price @ 10K: TBD; Price @ 1K: TBD; Vendor: NA; Vendor_Part_No: NA; eI Part#: TBD
R439 = 10_R_0: RES 5.6K OHM 1/10W 5% 0402 SMD; AVL_Part: AVL; Advansus_Part_Number: 10G212560114030; Avalue_Part_Number: E1050505620H; Distributor_name: DIGIKEY; Distributor_part_number: P5.6KJTR-ND; EIC Part#: 02_00169_01; Manufacture: Panasonic - ECG; Manufacture Part Number: ERJ-2GEJ562X; Manufacture(English): Panasonic - ECG; Manufacture_Part_Number: ERJ-2GEJ562X; Manufacturer: Panasonic - ECG; Manufacturer_Part_No: ERJ-2GEJ562X; Mfg: Panasonic Electronic Components; Mfg Part#: ERJ-2GEJ562X; Mfr_name: Panasonic - ECG; Mfr_part_number: ERJ-2GEJ562X; Package: 0402; Part_Number: 105A55601A-03; Price @ 1: 0.10000; Price @ 10K: 0.00347; Price @ 1K: 0.00672; ProcessType: SMT; Tolerance: 5%; Vendor: DIGIKEY; Vendor_Part_No: P5.6KJTR-ND; eI Part#: 02_00169_01
R440 = 10_R_0: RES 0.0 OHM 1/10W JUMP 0402 SMD; Characteristic: 5%; Distributor_name: DIGIKEY; Distributor_part_number: P0.0JCT-ND; EIC Part#: 02_00019_01; MOUNTED: <MOUNTED>; Manufacture: Panasonic - ECG; Manufacture Part Number: ERJ-2GE0R00X; Manufacture(English): Panasonic - ECG; Manufacture_Part_Number: ERJ-2GE0R00X; Manufacturer: Panasonic - ECG; Manufacturer_Part_No: ERJ-2GE0R00X; Mfg: Panasonic Electronic Components; Mfg Part#: 02_00019_01; Mfr_name: Panasonic - ECG; Mfr_part_number: ERJ-2GE0R00X; Package: 0402; Part_Number: 105A700004; Price @ 1: 0.05000; Price @ 10K: 0.00248; Price @ 1K: 0.00480; ProcessType: SMT; Tolerance: 5%; Vendor: DIGIKEY; Vendor_Part_No: P0.0JCT-ND; eI Part#: 02_00019_01
R442 = 10_R_0: RES 499 OHM 1/10W 1% 0603 SMD; Alt Mfg: Yageo; Alt Mfg Part#: RC0402FR-0710KL; Distributor_name: DIGIKEY; Distributor_part_number: P499HCT-ND; EIC Part#: 02_00806_01; Manufacture: Panasonic - ECG; Manufacture Part Number: ERJ-3EKF4990V; Manufacture(English): Panasonic - ECG; Manufacture_Part_Number: ERJ-3EKF4990V; Manufacturer: Panasonic - ECG; Manufacturer_Part_No: ERJ-3EKF4990V; Mfg Part#: 02_00806_01; Mfr_name: Panasonic - ECG; Mfr_part_number: ERJ-3EKF4990V; Oper. Temp. Range: -55C ~ 125C; Package: 0603; ProcessType: SMT; Remark: Alt part is 1/16W; RoHS: Yes; Tolerance: 1%; Vendor: DIGIKEY; Vendor Part#: P499HDKR-ND; Vendor_Part_No: P499HCT-ND; eI Part#: 02_00043_02
R443 = 10_R_0: RES 10K OHM 1/10W 1% 0402 SMD; Characteristic: 1%; Distributor_name: DIGIKEY; Distributor_part_number: P10.0KLCT-ND; EIC Part#: 02_00027_01; Manufacture: Panasonic - ECG; Manufacture Part Number: ERJ-2RKF1002X; Manufacture(English): Panasonic - ECG; Manufacture_Part_Number: ERJ-2RKF1002X; Manufacturer: Panasonic - ECG; Manufacturer_Part_No: ERJ-2RKF1002X; Mfg: PANASONIC ELECTRONIC COMPONENTS (VA); Mfg Part#: 02_00027_01; Mfr_name: Panasonic - ECG; Mfr_part_number: ERJ-2RKF1002X; Package: 0402; Part_Number: 105A50103A; Price @ 1: 0.10000; Price @ 10K: 0.00347; Price @ 1K: 0.00672; ProcessType: SMT; Tolerance: 1%; Vendor: DIGIKEY; Vendor_Part_No: P10.0KLCT-ND; eI Part#: 02_00027_01
R444 R774 = 10_R_0: RES 0.0 OHM 1/10W JUMP 0402 SMD; Characteristic: 5%; Distributor_name: DIGIKEY; Distributor_part_number: P0.0JCT-ND; EIC Part#: 02_00019_01; Manufacture: Panasonic - ECG; Manufacture Part Number: ERJ-2GE0R00X; Manufacture(English): Panasonic - ECG; Manufacture_Part_Number: ERJ-2GE0R00X; Manufacturer: Panasonic - ECG; Manufacturer_Part_No: ERJ-2GE0R00X; Mfg: Panasonic Electronic Components; Mfg Part#: 02_00019_01; Mfr_name: Panasonic - ECG; Mfr_part_number: ERJ-2GE0R00X; Package: 0402; Part_Number: 105A700004; Price @ 1: 0.05000; Price @ 10K: 0.00248; Price @ 1K: 0.00480; ProcessType: SMT; Tolerance: 5%; Vendor: DIGIKEY; Vendor_Part_No: P0.0JCT-ND; eI Part#: 02_00019_01
R450 R457 R783 = 10_R_0: RES 0.0 OHM 1/10W JUMP 0402 SMD; Characteristic: 5%; Distributor_name: DIGIKEY; Distributor_part_number: P0.0JCT-ND; EIC Part#: 02_00019_01; MOUNTED: NU; Manufacture: Panasonic - ECG; Manufacture Part Number: ERJ-2GE0R00X; Manufacture(English): Panasonic - ECG; Manufacture_Part_Number: ERJ-2GE0R00X; Manufacturer: Panasonic - ECG; Manufacturer_Part_No: ERJ-2GE0R00X; Mfg: Panasonic Electronic Components; Mfg Part#: 02_00019_01; Mfr_name: Panasonic - ECG; Mfr_part_number: ERJ-2GE0R00X; Mounting Status: NU; Mounting_Status: NU; Package: 0402; Part_Number: 105A700004; Price @ 1: 0.05000; Price @ 10K: 0.00248; Price @ 1K: 0.00480; ProcessType: SMT; Tolerance: 5%; Vendor: DIGIKEY; Vendor_Part_No: P0.0JCT-ND; eI Part#: 02_00019_01
R460 R471 = 10_R_0: RES 10K OHM 1/10W 1% 0402 SMD; Characteristic: 1%; Distributor_name: DIGIKEY; Distributor_part_number: P10.0KLCT-ND; EIC Part#: 02_00027_01; MOUNTED: <MOUNTED>; Manufacture: Panasonic - ECG; Manufacture Part Number: ERJ-2RKF1002X; Manufacture(English): Panasonic - ECG; Manufacture_Part_Number: ERJ-2RKF1002X; Manufacturer: Panasonic - ECG; Manufacturer_Part_No: ERJ-2RKF1002X; Mfg: PANASONIC ELECTRONIC COMPONENTS (VA); Mfg Part#: 02_00027_01; Mfr_name: Panasonic - ECG; Mfr_part_number: ERJ-2RKF1002X; Package: 0402; Part_Number: 105A50103A; Price @ 1: 0.10000; Price @ 10K: 0.00347; Price @ 1K: 0.00672; ProcessType: SMT; Tolerance: 1%; Vendor: DIGIKEY; Vendor_Part_No: P10.0KLCT-ND; eI Part#: 02_00027_01
R461 = 10_R_0: RES 4.7K OHM 1/10W 5% 0402 SMD; Alt Mfg: Yageo; Alt Mfg Part#: RC0402JR-074K7L; Distributor_name: DIGIKEY; Distributor_part_number: P4.7KJCT-ND; EIC Part#: 02_00023_01; Manufacture: Panasonic - ECG; Manufacture Part Number: ERJ-2GEJ472X; Manufacture(English): Panasonic - ECG; Manufacture_Part_Number: ERJ-2GEJ472X; Manufacturer: Panasonic - ECG; Manufacturer_Part_No: ERJ-2GEJ472X; Mfg Part#: 02_00023_01; Mfr_name: Panasonic - ECG; Mfr_part_number: ERJ-2GEJ472X; Oper. Temp. Range: -55C to 125C; Package: 0402; ProcessType: SMT; Remark: Alt part is 1/16W; RoHS: Yes; Tolerance: 1%; Vendor: DIGIKEY; Vendor Part#: P4.7KJCT-ND; Vendor_Part_No: P4.7KJCT-ND; eI Part#: 02_00023_01
R462 R467 = 10_R_0: RES 49.9 OHM 1/10W 1% 0402 SMD; Characteristic: 1%; Distributor_name: DIGIKEY; Distributor_part_number: P49.9LCT-ND; EIC Part#: 02_00025_01; Manufacture: Panasonic - ECG; Manufacture Part Number: ERJ-2RKF49R9X; Manufacture(English): Panasonic - ECG; Manufacture_Part_Number: ERJ-2RKF49R9X; Manufacturer: Panasonic - ECG; Manufacturer_Part_No: ERJ-2RKF49R9X; Mfg: Panasonic - ECG; Mfg Part#: ERJ-2RKF49R9X; Mfr_name: Panasonic - ECG; Mfr_part_number: ERJ-2RKF49R9X; Package: 0402; Part_Number: 105A549964-03; Price @ 1: 0.10000; Price @ 10K: 0.00347; Price @ 1K: 0.00672; ProcessType: SMT; Tolerance: 1%; Vendor: DIGIKEY; Vendor Part#: P49.9LCT-ND; Vendor_Part_No: P49.9LCT-ND; eI Part#: 02_00025_01
R770 = 10_R_0: RES 3.16K OHM 1/10W 1% 0402 SMD; AVL_Part: AVL; Advansus_Part_Number: 10G212316114030; Avalue_Part_Number: E1050531610H; Distributor_name: DIGIKEY; Distributor_part_number: P3.16KLCT-ND; EIC Part#: 02_00247_01; Manufacture: Panasonic - ECG; Manufacture Part Number: ERJ-2RKF3161X; Manufacture(English): Panasonic - ECG; Manufacture_Part_Number: ERJ-2RKF3161X; Manufacturer: Panasonic - ECG; Manufacturer_Part_No: ERJ-2RKF3161X; Mfg: Panasonic Electronic Components; Mfg Part#: 02_00247_01; Mfr_name: Panasonic - ECG; Mfr_part_number: ERJ-2RKF3161X; Package: 0402; Part_Number: 1000001652-03; Price @ 1: 0.10000; Price @ 10K: 0.00347; Price @ 1K: 0.00672; ProcessType: SMT; Tolerance: 1%; Vendor: DIGIKEY; Vendor_Part_No: P3.16KLCT-ND; eI Part#: 02_00018_05
R784 R785 = 10_R_0: RES 1.00K OHM 1/10W 1% 0402 SMD; Distributor_name: DIGIKEY; Distributor_part_number: P1.00KLCT-ND; EIC Part#: 02_00045_01; Manufacture: Panasonic - ECG; Manufacture Part Number: ERJ-2RKF1001X; Manufacture(English): Panasonic - ECG; Manufacture_Part_Number: ERJ-2RKF1001X; Manufacturer: Panasonic - ECG; Manufacturer_Part_No: ERJ-2RKF1001X; Mfg Part#: 02_00045_01; Mfr_name: Panasonic - ECG; Mfr_part_number: ERJ-2RKF1001X; Price @ 1: 0.10000; Price @ 10K: 0.00347; Price @ 1K: 0.00672; Vendor: DIGIKEY; Vendor_Part_No: P1.00KLCT-ND; eI Part#: 02_00045_01
R787 = 10_R_0: RES 1.00K OHM 1/10W 1% 0402 SMD; Characteristic: 1%; Distributor_name: DIGIKEY; Distributor_part_number: P1.00KLCT-ND; EIC Part#: 02_00045_01; MOUNTED: <MOUNTED>; Manufacture: Panasonic - ECG; Manufacture Part Number: ERJ-2RKF1001X; Manufacture(English): Panasonic - ECG; Manufacture_Part_Number: ERJ-2RKF1001X; Manufacturer: Panasonic - ECG; Manufacturer_Part_No: ERJ-2RKF1001X; Mfg: Panasonic Electronic Components; Mfg Part#: 02_00045_01; Mfr_name: Panasonic - ECG; Mfr_part_number: ERJ-2RKF1001X; Package: 0402; Part_Number: 105A510014; Price @ 1: 0.10000; Price @ 10K: 0.00347; Price @ 1K: 0.00672; ProcessType: SMT; Tolerance: 1%; Vendor: DIGIKEY; Vendor_Part_No: P1.00KLCT-ND; eI Part#: 02_00045_01
TP103 TP108 = 00_TP28_0: TEST PAD TP; Advansus_Part_Number: 0030000003; Avalue_Part_Number: 0030000003; Distributor_name: NA; Distributor_part_number: NA; EIC Part#: NA; Manufacture: NA; Manufacture Part Number: NA; Manufacture(English): NA; Manufacture_Part_Number: NA; Manufacturer: NA; Manufacturer_Part_No: NA; Mfg: NA; Mfg Part#: NA; Mfr_name: NA; Mfr_part_number: NA; Part_Number: 0030000003; Price @ 1: NA; Price @ 10K: NA; Price @ 1K: NA; ProcessType: SMT; Vendor: NA; Vendor_Part_No: NA; eI Part#: NA
U41 = 141_TI_REF5050AIDR_0: IC VREF SERIES PREC 2.5V 8VSSOP; AVL_Part: AVL; Distributor_name: DIGIKEY; Distributor_part_number: 296-24498-1-ND; EIC Part#: TBD; Manufacture: TI; Manufacture Part Number: REF5025AIDGKT; Manufacture(English): TI; Manufacture_Part_Number: REF5025AIDGKT; Manufacturer: TI; Manufacturer_Part_No: REF5025AIDGKT; Mfg: TI; Mfg Part#: TBD; Mfr_name: TI; Mfr_part_number: REF5025AIDGKT; Package: SOIC8; Part_Number: 1410023275-01; Price @ 1: 4.02000; Price @ 1K: 2.58076; ProcessType: SMT; Vendor: DIGIKEY; Vendor_Part_No: 296-24498-1-ND; eI Part#: 01_01129_01
U47 = 141_TI_CDCM6208_1: IC CLK GEN 2:8 LOW JITTER 48VQFN; AVL_Part: AVL; Distributor_name: DIGIKEY; Distributor_part_number: 296-36574-1-ND; EIC Part#: 01_01119_01; Manufacture: TI; Manufacture(English): TI; Manufacturer: TI; Mfg: TI; Mfg Part#: 01_01119_01; Mfr_name: TI; Oper. Temp. Range: -40°C ~ 85°C; Package: VQFN48; Price @ 1: 12.07000; Price @ 10K: 5.85000; Price @ 1K: 5.96700; ProcessType: SMT; RoHS: Yes; Vendor: DIGIKEY; Vendor Part#: CDCM6208V1RGZR-ND; Vendor_Part_No: 296-36574-1-ND; eI Part#: TBD
U49 = 141_TI_DAC8550_0: IC DAC 16BIT VOLT-OUT 8VSSOP; Distributor_name: DIGIKEY; Distributor_part_number: 296-19621-6-ND; EIC Part#: TBD; Manufacture: TI; Manufacture Part Number: DAC8550IBDGKT; Manufacture(English): TI; Manufacture_Part_Number: DAC8550IBDGKT; Manufacturer: TI; Manufacturer_Part_No: DAC8550IBDGKT; Mfg: TI; Mfg Part#: TBD; Mfr_name: TI; Mfr_part_number: DAC8550IBDGKT; Package: MSOP8; Part_Number: 1410023038-01; Price @ 1: 7.97000; Price @ 1K: 5.90190; ProcessType: SMT; Vendor: DIGIKEY; Vendor_Part_No: 296-19621-6-ND; eI Part#: 01_00419_01
U71 = 141_TI_SN74AVC4T245PWR_1: IC BUS TRANSCVR 4BIT 16TSSOP; Distributor_name: DIGIKEY; Distributor_part_number: 296-18056-1-ND; EIC Part#: 01_00045_01; Manufacture: TI; Manufacture Part Number: SN74AVC4T245PWR; Manufacture(English): TI; Manufacture_Part_Number: SN74AVC4T245PWR; Manufacturer: TI; Manufacturer_Part_No: SN74AVC4T245PWR; Mfg: TI; Mfg Part#: 01_00045_01; Mfr_name: TI; Mfr_part_number: SN74AVC4T245PWR; Package: TSSOP16; Part_Number: 1410012118; Price @ 1: 1.08000; Price @ 10K: 0.42000; Price @ 1K: 0.46500; ProcessType: SMT; Vendor: DIGIKEY; Vendor_Part_No: 296-18056-1-ND; eI Part#: TBD

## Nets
AVCC3V3_1: C246.1 C248.1 C249.1 C738.1 FB8.2 ; also on sheet 2
AVCC3V3_2: C177.1 C178.1 C179.1 C538.1 FB5.2 PHY1.20(AVDD33_1) PHY1.25(AVDD33_2) PHY1.36(REG_IN)
AVDD1V8_1: C223.1 C224.1 C225.1 C226.1 C264.1 C267.1 C284.1 C736.1 C737.1 C739.1 C740.1 C753.1 ; also on sheet 2
AVDD1V8_2: C168.1 C169.1 C170.1 C171.1 C188.1 C189.1 C201.1 C536.1 C537.1 C539.1 C540.1 C544.1 PHY1.3(AVDD18_1) PHY1.19(AVDD18_2) PHY1.26(AVDD18_3) PHY1.35(AVDDC18) PHY1.38(AVDD18_4) PHY1.39(AVDD18_OUT)
DVDD1V0_1: C211.1 C217.1 C229.1 C231.1 C283.1 ; also on sheet 2
DVDD1V0_2: C143.1 C156.1 C162.1 C166.1 C200.1 PHY1.6(DVDD_1) PHY1.40(DVDD_OUT) PHY1.42(DVDD_2)
GND: B5.2(GND) B6.2(GND) B7.2(GND) B8.2(GND) B10.2(GND) B11.2(GND) C143.2 C156.2 C162.2 C166.2 C168.2 C169.2 C170.2 C171.2 C173.1 C174.1 C177.2 C178.2 C179.2 C180.2 C186.1 C188.2 C189.2 C192.2 C195.2 C200.2 C201.2 C211.2 C217.2 C223.2 C224.2 C225.2 C226.2 C229.2 C231.2 C246.2 C248.2 C249.2 C250.2 C264.2 C267.2 C283.2 C284.2 C336.1 C337.2 C347.1 C348.2 C360.1 C362.2 C365.1 C536.2 C537.2 C538.2 C539.2 C540.2 C544.2 C736.2 C737.2 C738.2 C739.2 C740.2 C753.2 C810.2 C817.2 C822.2 C850.2 C854.1 C860.1 C872.2 C874.2 C875.2 C884.2 C885.1 C893.2 C898.1 C899.1 C903.1 C907.1 C909.1 C917.1 C919.1 C927.1 C929.1 C930.1 C931.1 C932.1 C969.2 C970.2 C971.2 C972.2 C973.2 C974.2 C975.2 C976.2 FB7.1 OSC3.4(GND1) OSC3.10(GND2) PHY1.10(VDDO_SEL) PHY1.57(VSS) Q17.4(GND) Q17.9(EPAD) R222.2 R235.1 R238.1 R241.1 R244.1 R257.1 R260.1 R440.2 R444.2 R450.2 R460.1 R471.1 R770.2 R774.2 R852.2 U41.4(GND) U47.12(SEC_REFN) U47.49(GND_EPAD) U47.50(THERMAL_VIA_1) U47.51(THERMAL_VIA_2) U47.52(THERMAL_VIA_3) U47.53(THERMAL_VIA_4) U47.54(THERMAL_VIA_5) U47.55(THERMAL_VIA_6) U47.56(THERMAL_VIA_7) U47.57(THERMAL_VIA_8) U47.58(THERMAL_VIA_9) U47.59(THERMAL_VIA_10) U47.60(THERMAL_VIA_11) U47.61(THERMAL_VIA_12) U47.62(THERMAL_VIA_13) U47.63(THERMAL_VIA_14) U47.64(THERMAL_VIA_15) U47.65(THERMAL_VIA_16) U49.8(GND) U71.2(1DIR) U71.3(2DIR) U71.8(GND1) U71.9(GND2) U71.14(2~{OE}) U71.15(1~{OE}) Y3.2 Y3.4 ; also on sheet 1 2 3 4 5 6 8 10 13 14 15 16 17 18 19 20 21 22 24 25 26 27 28 29 33 34 35 36 37 40 41 42 43 45 46 47
GND_LAN: CN4.10B(GND) CN4.SH3(P2_PTH_1) CN4.SH4(P2_PTH_2) FB7.2 ; also on sheet 2
VCC1V8: C860.2 U71.16(VCCB) ; also on sheet 2 6 8 19 21 22 25 26 27 29 33 34 36 37 41
VCC1V8_TCT: R258.1 ; also on sheet 2
VCC2V5: C971.1 C972.1 C973.1 C974.1 C975.1 C976.1 CN4.11B(P2_COMMON1) CN4.13B(P2_COMMON2) PHY1.11(VDDO_1) PHY1.49(VDDO_2) PHY1.52(VDDO_3) Q17.1(VOUT) R272.2 R853.1 TP125.1 ; also on sheet 2
VCC3V3_AUX: B5.1(IN) B6.1(IN) B7.1(IN) B8.1(IN) B10.1(IN) B11.1(IN) C180.1 C250.1 C810.1 C969.1 C970.1 FB5.1 FB8.1 Q17.8(VIN) R247.2 R439.1 R443.1 R784.1 R785.1 R854.2 U71.1(VCCA) ; also on sheet 2 4 6 8 13 16 18 19 22 25 26 27 28 29 33 35 37 40 45 47
VCC3V3_AUX_F1: B8.3(OUT) C899.2 C903.2 C907.2 C909.2 C917.2 C919.2 C927.2 C929.2 C930.2 C931.2 C932.2 U47.7(VDD_PRI_REF) U47.10(VDD_SEC_REF) U47.13(VDD_Y0_Y1_1) U47.18(VDD_Y0_Y1_2) U47.19(VDD_Y2_Y3_1) U47.24(VDD_Y2_Y3_2) U47.27(VDD_Y4) U47.30(VDD_Y5) U47.31(VDD_Y6) U47.34(VDD_Y7) U47.48(DVDD)
VCCPLLA1A: B5.3(OUT) C336.2 C337.1 U47.37(VDD_PLL1)
VCCPLLA1B: B11.3(OUT) C884.1 C885.2 U47.38(VDD_PLL2) U47.39(VDD_VCO)
19.2MHZ_SLAVECLKN: U47.28(Y5_N) ; also on sheet 16
19.2MHZ_SLAVECLKP: U47.29(Y5_P) ; also on sheet 16
BMC_SPI0_CLK_FPGA_3V3: U47.5(SCL/PIN4) ; also on sheet 5 13 27
BMC_SPI0_CS1#: U47.4(SCS/AD1/PIN3) ; also on sheet 5
BMC_SPI0_MISO_FPGA_3V3: U47.3(SDO/AD0/PIN2) ; also on sheet 5 13 27
BMC_SPI0_MOSI_FPGA_3V3: U47.2(SDI/SDA/PIN1) ; also on sheet 5 13 27
BUF_122.88MHZ_CLKN: U47.16(Y1_N) ; also on sheet 16
BUF_122.88MHZ_CLKP: U47.17(Y1_P) ; also on sheet 16
CDCM1_PLL_LOCK_3V3_BMC: U47.46(STATUS0) ; also on sheet 5
CDCM1_PRI_REFN: C915.1 ; also on sheet 16
CDCM1_PRI_REFP: C904.1 ; also on sheet 16
CDCM1_REF_SEL_FPGA_3V3_EXP4: R457.2 ; also on sheet 27
CDCM1_REFCLK1_PD#_FPGA_3V3_EXP4: R783.2 ; also on sheet 27
CDCM_CLKRSTZ_3V3_BMC: U47.44(RESETN/PWR) ; also on sheet 5 13
CLK1_ELF: C875.1 R442.1 U47.41(ELF)
CLK1_SYNC: R443.2 U47.42(SYNCN)
DAC_SSPCK_3.3V: U49.6(SCLK) U71.6(2A1)
DAC_SSPCS2_3.3V: U49.5(~{SYNC}) U71.5(1A2)
DAC_VOUT: C360.2 R787.2 TP108.1 U49.3(VFB) U49.4(VOUT)
FPGA_CLK_N: U47.25(Y4_N) ; also on sheet 28
FPGA_CLK_P: U47.26(Y4_P) ; also on sheet 28
PHY2_LED_0: PHY1.14(LED[0]) R259.2 R655.1
PHY2_LED_1: PHY1.13(LED[1]) R610.1
PHY2_MDI0_N: CN4.1B(P2_TD1-) PHY1.27(MDI[0]_N)
PHY2_MDI0_P: CN4.2B(P2_TD1+) PHY1.28(MDI[0]_P)
PHY2_MDI1_N: CN4.3B(P2_TD2-) PHY1.23(MDI[1]_N)
PHY2_MDI1_P: CN4.4B(P2_TD2+) PHY1.24(MDI[1]_P)
PHY2_MDI2_N: CN4.5B(P2_TD3-) PHY1.21(MDI[2]_N)
PHY2_MDI2_P: CN4.6B(P2_TD3+) PHY1.22(MDI[2]_P)
PHY2_MDI3_N: CN4.7B(P2_TD4-) PHY1.17(MDI[3]_N)
PHY2_MDI3_P: CN4.8B(P2_TD4+) PHY1.18(MDI[3]_P)
PHY_INT2#_FPGA_3V3_EXP4_2V5: PHY1.12(LED[2]/INTn) R272.1 ; also on sheet 2
PHY_RSTz_2V5: PHY1.16(RESETn) ; also on sheet 2
PRI_REFN: C915.2 R467.1 U47.9(PRI_REFN)
PRI_REFP: C904.2 R462.1 U47.8(PRI_REFP)
SGMII1_RXN_SOC: PHY1.5(SOUT_N) ; also on sheet 2
SGMII1_RXP_SOC: PHY1.4(SOUT_P) ; also on sheet 2
SGMII1_TXN_SOC: C203.1 ; also on sheet 2
SGMII1_TXN_SOC_NET: C203.2 PHY1.2(SIN_N)
SGMII1_TXP_SOC: C202.1 ; also on sheet 2
SGMII1_TXP_SOC_NET: C202.2 PHY1.1(SIN_P)
SOC_MDC_2V5: PHY1.7(MDC) ; also on sheet 2 18
SOC_MDIO_2V5: PHY1.8(MDIO) ; also on sheet 2 18
SOC_SPI1_CLK: U71.11(2B1) ; also on sheet 28 29
SOC_SPI1_MOSI: U71.10(2B2) ; also on sheet 28 29
SOC_SPI1SCS0: U71.12(1B2) ; also on sheet 29
SOC_SSPMOSI_3.3V: U49.7(DIN) U71.7(2A2)
SOC_TSREFCLKN: U47.33(Y6_N) ; also on sheet 29
SOC_TSREFCLKP: U47.32(Y6_P) ; also on sheet 29
SYS_CLKN: U47.15(Y0_N) ; also on sheet 16
SYS_CLKN_FMC1: U47.22(Y3_N) ; also on sheet 43
SYS_CLKN_FMC2: U47.21(Y2_N) ; also on sheet 46
SYS_CLKP: U47.14(Y0_P) ; also on sheet 16
SYS_CLKP_FMC1: U47.23(Y3_P) ; also on sheet 43
SYS_CLKP_FMC2: U47.20(Y2_P) ; also on sheet 46
SYSREF_DIVCLK_N: U47.36(Y7_N) ; also on sheet 28
SYSREF_DIVCLK_P: U47.35(Y7_P) ; also on sheet 28
VCTCXO_19.2M: C350.2 R471.2 U47.11(SEC_REFP)
N17272679: C334.1 R440.1
N17272964: C872.1 R439.2 R462.2 R467.2 R770.1
N17273150: R444.1 U47.1(SI_MODE0)
N17273154: TP103.1 U47.45(STATUS1/PIN0)
N17273170: R450.1 R457.1 R785.2 U47.6(REF_SEL)
N17273179: C334.2 U47.40(REG_CAP)
N17273195: R774.1 U47.47(SI_MODE1)
N17274113: B7.3(OUT) C362.1 C365.2 U49.1(VDD)
N17274213: B6.3(OUT) C893.1 C898.2 OSC3.9(VDD) R461.2
N17274274: C347.2 OSC3.1(NC/VCO) R460.2 R787.1
N17274366: B10.3(OUT) C850.1 C854.2 U41.2(VIN)
N17274408: C817.1 U41.5(TRIM/NR)
N17274432: C822.1 U41.6(VOUT) U49.2(VREF)
N18034036: PHY1.9(CLK125) TP59.1
N18034073: PHY1.30(RSET) R222.1
N18034098: PHY1.29(TSTPT) TP51.1
N18034100: C174.2 PHY1.33(XTAL_OUT) Y3.3
N18034117: C173.2 PHY1.34(XTAL_IN) Y3.1
N18034206: C165.1 PHY1.41(REGCAP2)
N18034212: C165.2 PHY1.37(REGCAP1)
N18034232: PHY1.15(CONFIG) R247.1 R259.1
N18034319: PHY1.31(HSDAC_N) TP50.1
N18034352: PHY1.32(HSDAC_P) TP48.1
N18034354: PHY1.53(TX_CLK) R241.2
N18034356: PHY1.56(TX_CTRL) R260.2
N18034358: PHY1.55(TXD[3]) R257.2
N18034360: PHY1.54(TXD[2]) R244.2
N18034377: PHY1.51(TXD[1]) R238.2
N18034379: PHY1.50(TXD[0]) R235.2
N18036253: CN4.12B(P2_GREEN) R655.2
N18036255: CN4.14B(P2_ORANGE) R610.2
N18151944: C874.1 R442.2
N20997985: C186.2 C192.1 C195.1 CN4.9B(P2_VCC) R258.2
N21317344: OSC3.5(OUT_DIS#) R461.1
N21318268: C348.1 OSC3.7(NC/VCFILTER)
N21318701: C350.1 OSC3.6(RFOUT)
N21671563: R783.1 R784.2 U47.43(PDN)
N22857346: Q17.3(FB) R852.1 R853.2
N22857352: Q17.5(EN) R854.1

Not connected (* = marked no-connect by the designer): OSC3 2(NC1)* 3(DNC)* 8(NC2)*; PHY1 43(RX_CTRL)* 44(RXD[0])* 45(RXD[1])* 46(RX_CLK)* 47(RXD[2])* 48(RXD[3])*; Q17 2(NC1)* 6(NC2)* 7(NC3)*; U41 1(DNC_0)* 3(TEMP)* 7(NC)* 8(DNC_1)*; U71 4(1A1)* 13(1B1)*

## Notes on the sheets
sheet 11
- CDCM62008 Clk1, 122.88/19.2, Power Filter for Clock,
  VCTXCO, SPI 1.8/3.3v for 1588 DAC, VRef, 1588DAC
- STATUS0 outputs the PLL_LOCK signal
  STATUS1 the LOSS OF REFERENCE.
- REF SEL:
  0 - PRI REF CLOCK
  1 - SEC REF CLOCK
- 122.88MHz Output
- from VCTCXO19.2Mhz
- 122.88MHz Output
- 122.88MHz Output
- 122.88MHz Output
- 122.88MHz Output
- 19.2MHz Output
- 245.76MHz Output
- 122.88MHz Output
- [Note]layout would place R440 and C334 close to U47.
- Serial Interface Mode or Pin Mode Selection
- MCU_SI_MODE[1:0]
- DESCRIPTION
- pull-up resister
- Synthesizer mode (high loop bandwidth)
  CDCM6208V1:
  With C1=100pF, R2=500, C2=22nF and
  Internal components R3=100, C3=242.5pF,
  fPFD=25MHz, and ICP=2.5mA:
  Loop bandwidth ~ (337kHz)
- 00
- SPI MODE
- (Default)
- 01
- I2C MODE
- 10
- PIN MODE (NO SERIAL PROGRAMMING)
- 11
- RESEERVED
- SPI1 from SoC for
  DAC
sheet 12
- Ethernet PHY, Magnetics for 2 channel/ Tx/Rx
- ETHERNET PHY 2
- Magnetics for 2 channel/ Tx/Rx
- PHY ADDRESS :- 0x1
- 2.5V @ 0.8A
- R1
- R2
- Vout = (R1+R2)*VFB/R2
          = (39.2+36.5k)*1.2/36.5k
          = 2.5V
